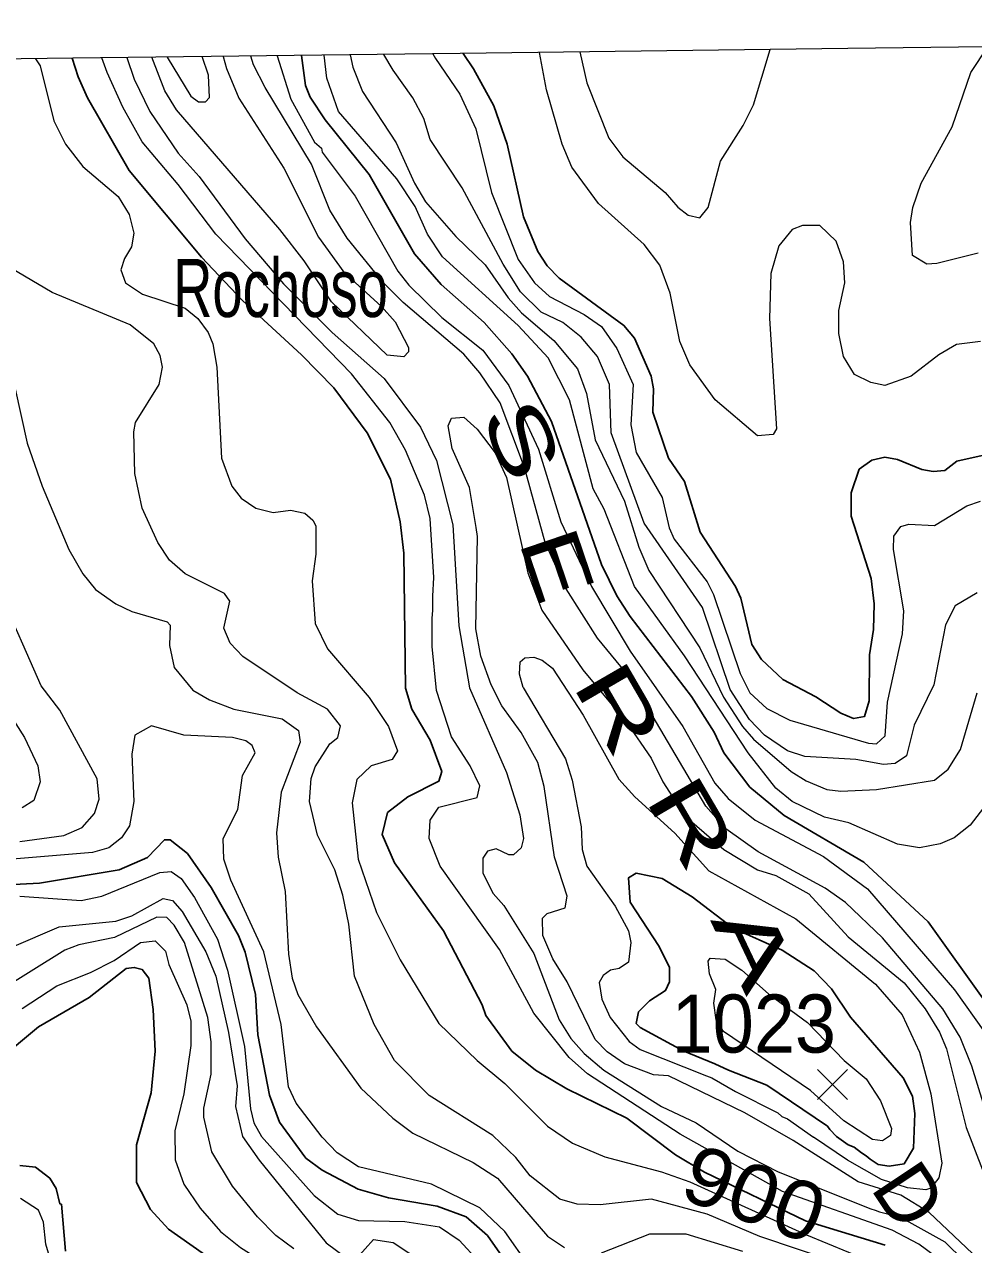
# Model space of a CAD drawing. Extents: x 265 to 291.4, y 7731.5 to 7759.6.
# Drawn here: x 281.951 to 283.257, y 7757.817 to 7759.497 of the extents above; entities that cross this region are included whole.
import ezdxf
from ezdxf.enums import TextEntityAlignment as Align

# ---------------------------------------------------------------- set-up
doc = ezdxf.new("R2010")
doc.units = 0
doc.header["$LTSCALE"] = 0.032
for name, color, linetype, lineweight in [('1', 7, 'Continuous', 25), ('2', 7, 'Continuous', 13), ('21', 7, 'Continuous', 25), ('61', 7, 'Continuous', 13), ('63', 7, 'Continuous', 25)]:
    doc.layers.add(name, color=color, linetype=linetype, lineweight=lineweight)

msp = doc.modelspace()

# ---------------------------------------------------------------- linework, layer by layer
at = {"layer": '1'}
for points in [[(283.1354, 7757.8165), (283.0256, 7757.85), (282.8865, 7757.9171), (282.8467, 7757.941), (282.7798, 7757.9915), (282.697, 7758.0321), (282.6541, 7758.0576), (282.6214, 7758.0838), (282.5856, 7758.1331), (282.5809, 7758.1475), (282.5276, 7758.2493), (282.46, 7758.3432), (282.4433, 7758.3821), (282.4504, 7758.4123), (282.4783, 7758.4338), (282.5212, 7758.4553), (282.5252, 7758.4688), (282.5093, 7758.5118), (282.4838, 7758.5548), (282.4751, 7758.5834), (282.4727, 7758.7695), (282.4679, 7758.8125), (282.4544, 7758.8714), (282.4226, 7758.935), (282.3764, 7758.997), (282.3319, 7759.0424), (282.2508, 7759.1171), (282.1943, 7759.1768), (282.0948, 7759.2961), (282.0376, 7759.3964), (282.0248, 7759.425), (282.0167, 7759.4507)], [(282.3319, 7759.4547), (282.3374, 7759.4131), (282.344, 7759.3972), (282.3645, 7759.3661), (282.425, 7759.2906), (282.4878, 7759.1816), (282.5244, 7759.1394), (282.5833, 7759.0869), (282.6214, 7759.044), (282.6429, 7759.0129), (282.6763, 7758.9509), (282.7447, 7758.7536), (282.7662, 7758.7107), (282.7845, 7758.682), (282.8688, 7758.5723), (282.8999, 7758.5229), (282.9134, 7758.4943), (282.9492, 7758.4474), (282.9961, 7758.4083), (283.1059, 7758.3439), (283.1942, 7758.262), (283.2761, 7758.1475)], [(283.281, 7758.9066), (283.234, 7758.896), (283.2173, 7758.8833), (283.2014, 7758.8817), (283.1855, 7758.8848), (283.1521, 7758.8984), (283.1346, 7758.9015), (283.1171, 7758.8976), (283.0995, 7758.8849), (283.0884, 7758.8523), (283.0884, 7758.8204), (283.1162, 7758.7345), (283.1202, 7758.6995), (283.1194, 7758.6645), (283.1138, 7758.6295), (283.1131, 7758.5659), (283.1067, 7758.5444), (283.0916, 7758.542), (283.0741, 7758.5492), (283.0399, 7758.5714), (282.9946, 7758.5953), (282.9651, 7758.6232), (282.9516, 7758.6438), (282.9365, 7758.7075), (282.9293, 7758.7234), (282.8808, 7758.7982), (282.8593, 7758.8682), (282.837, 7758.9), (282.8155, 7758.9636), (282.8163, 7758.9955), (282.8132, 7759.013), (282.7901, 7759.0655), (282.7758, 7759.083), (282.6867, 7759.1482), (282.67, 7759.1649), (282.6572, 7759.1848), (282.6374, 7759.2325), (282.6151, 7759.3327), (282.5968, 7759.3852), (282.5689, 7759.4362), (282.5547, 7759.4575)], [(281.8825, 7758.3105), (281.9716, 7758.3153), (282.0813, 7758.3336), (282.1203, 7758.3503), (282.1434, 7758.3749), (282.1513, 7758.3749), (282.1752, 7758.3559), (282.2078, 7758.3089), (282.2452, 7758.2429), (282.2547, 7758.2199), (282.269, 7758.1618), (282.2722, 7758.1061), (282.2881, 7758.0234), (282.3017, 7757.986), (282.3382, 7757.9367), (282.3605, 7757.9199), (282.4099, 7757.8937), (282.452, 7757.8817), (282.5189, 7757.8706), (282.5586, 7757.8555), (282.5881, 7757.83), (282.6819, 7757.6956)], [(282.2881, 7757.741), (282.1489, 7757.8388), (282.1243, 7757.8658), (282.1052, 7757.9032), (282.1052, 7757.955), (282.1251, 7758.0266), (282.1306, 7758.0838), (282.1282, 7758.1411), (282.1219, 7758.1841), (282.1131, 7758.196), (282.102, 7758.1991), (282.0909, 7758.1976), (282.04, 7758.1578), (281.97, 7758.1172), (281.9143, 7758.0711)], [(281.9445, 7757.9263), (281.966, 7757.9239), (281.9859, 7757.9088), (281.9946, 7757.8945), (281.9994, 7757.8738), (282.0018, 7757.873), (282.0073, 7757.8086)]]:
    msp.add_lwpolyline(points, dxfattribs=at)
msp.add_lwpolyline([(283.0876, 7758.1307), (283.0613, 7758.1697), (283.0375, 7758.1944), (282.9937, 7758.223), (282.9261, 7758.2532), (282.8696, 7758.2962), (282.8283, 7758.3216), (282.7925, 7758.3288), (282.7821, 7758.3225), (282.7845, 7758.2891), (282.8243, 7758.2278), (282.8386, 7758.1992), (282.8386, 7758.1793), (282.833, 7758.1673), (282.8108, 7758.153), (282.7957, 7758.1379), (282.7925, 7758.122), (282.798, 7758.1164), (282.8571, 7758.0841), (282.9009, 7758.0662), (282.9198, 7758.0575), (282.9723, 7758.0368), (283.0558, 7757.9804), (283.0593, 7757.9761), (283.0685, 7757.9661), (283.0844, 7757.955), (283.0925, 7757.9518), (283.1027, 7757.9438), (283.1091, 7757.9399), (283.1146, 7757.935), (283.1258, 7757.9279), (283.1409, 7757.9255), (283.1616, 7757.9287), (283.1743, 7757.9502), (283.1759, 7757.9979), (283.1727, 7758.0218), (283.16, 7758.0472)], close=True, dxfattribs=at)
at = {"layer": '2'}
msp.add_line((282.5741, 7758.7923), (282.5726, 7758.8047), dxfattribs=at)
for points in [[(283.2634, 7759.1824), (283.2062, 7759.1681), (283.1926, 7759.1673), (283.1727, 7759.1792), (283.1703, 7759.2246), (283.1735, 7759.2452), (283.1847, 7759.2786), (283.2276, 7759.3566), (283.2531, 7759.4314), (283.2765, 7759.4665)], [(281.9662, 7759.4501), (281.9726, 7759.4404), (281.9914, 7759.3646), (282.0073, 7759.3327), (282.0312, 7759.3017), (282.0797, 7759.2603), (282.0948, 7759.2357), (282.1012, 7759.2102), (282.098, 7759.1911), (282.0885, 7759.1752), (282.0837, 7759.1593), (282.0901, 7759.1418), (282.1132, 7759.1259), (282.172, 7759.1068), (282.1895, 7759.0925), (282.2038, 7759.0734), (282.2102, 7759.0575), (282.2158, 7759.0257), (282.2221, 7758.9), (282.2364, 7758.8618), (282.2492, 7758.8451), (282.2691, 7758.8316), (282.2929, 7758.8252), (282.3168, 7758.8284), (282.3367, 7758.8244), (282.3478, 7758.8149), (282.3518, 7758.8069), (282.3518, 7758.7679), (282.347, 7758.7314), (282.351, 7758.6725), (282.3677, 7758.6375), (282.425, 7758.5707), (282.452, 7758.5309), (282.464, 7758.4975), (282.4568, 7758.4855), (282.4282, 7758.4768), (282.4083, 7758.4577), (282.4019, 7758.4259), (282.4099, 7758.3479), (282.4353, 7758.2747), (282.4679, 7758.2095), (282.5212, 7758.122), (282.5737, 7758.0711), (282.6119, 7758.0393), (282.6708, 7757.9804), (282.705, 7757.9573), (282.7495, 7757.9382), (282.8275, 7757.9176), (282.8665, 7757.904), (283.0269, 7757.8309), (283.1139, 7757.7951)], [(283.2149, 7757.7935), (283.1815, 7757.8181), (283.1449, 7757.8372), (282.9941, 7757.8907), (282.853, 7757.9693), (282.7257, 7758.0528), (282.7002, 7758.0751), (282.6517, 7758.1363), (282.6047, 7758.2238), (282.5228, 7758.3384), (282.5077, 7758.3766), (282.5093, 7758.402), (282.5212, 7758.4195), (282.5737, 7758.433), (282.5777, 7758.4489), (282.5642, 7758.4768), (282.5387, 7758.5166), (282.518, 7758.5802), (282.5117, 7758.6407), (282.512, 7758.6796), (282.5127, 7758.6909), (282.5127, 7758.7102), (282.5141, 7758.7361), (282.5093, 7758.8173), (282.5013, 7758.8491), (282.4751, 7758.9111), (282.4536, 7758.9493), (282.4011, 7759.0161), (282.2142, 7759.2086), (282.1625, 7759.2771), (282.1131, 7759.3359), (282.0861, 7759.3836), (282.0646, 7759.4314), (282.0574, 7759.4512)], [(282.0919, 7759.4517), (282.102, 7759.4218), (282.1235, 7759.3773), (282.1625, 7759.32), (282.1911, 7759.2882), (282.2547, 7759.2023), (282.3072, 7759.1402), (282.3741, 7759.0734), (282.4457, 7759.0098), (282.4958, 7758.9427), (282.5177, 7758.8969), (282.5402, 7758.8085), (282.5486, 7758.6696)], [(282.2243, 7759.4533), (282.2288, 7759.4365), (282.2461, 7759.396), (282.3078, 7759.2996), (282.3556, 7759.2046), (282.3902, 7759.1562), (282.4423, 7759.109), (282.4609, 7759.0877), (282.4795, 7759.0525), (282.4795, 7759.0465), (282.4728, 7759.0399), (282.4502, 7759.0419), (282.3733, 7759.1156), (282.3359, 7759.172), (282.3025, 7759.215), (282.1601, 7759.3797), (282.1442, 7759.4059), (282.126, 7759.4521)], [(282.1471, 7759.4524), (282.1799, 7759.3987), (282.1905, 7759.3908), (282.1998, 7759.3908), (282.2055, 7759.3968), (282.2042, 7759.4273), (282.1954, 7759.453)], [(283.3031, 7757.9055), (283.2543, 7758.063), (283.2384, 7758.1029), (283.2145, 7758.1421), (283.1314, 7758.2397), (283.0805, 7758.2883), (283.0526, 7758.3081), (282.9603, 7758.3583), (282.9158, 7758.3901), (282.8887, 7758.4211), (282.7845, 7758.5977), (282.7392, 7758.6526), (282.6962, 7758.7202), (282.6676, 7758.7839), (282.639, 7758.8873), (282.6055, 7758.9764), (282.5777, 7759.0177), (282.5554, 7759.0432), (282.4718, 7759.1143), (282.4449, 7759.1415), (282.3951, 7759.2033), (282.3712, 7759.2418), (282.346, 7759.305), (282.2819, 7759.4106), (282.266, 7759.4418), (282.2624, 7759.4538)], [(282.2987, 7759.4543), (282.3173, 7759.3945), (282.3502, 7759.3351), (282.3597, 7759.3272), (282.3605, 7759.3216), (282.4059, 7759.2611), (282.4647, 7759.1577), (282.4799, 7759.1386), (282.5252, 7759.0941), (282.5817, 7759.0487), (282.6175, 7759.0002), (282.6581, 7758.9127), (282.6891, 7758.8125), (282.7312, 7758.7234), (282.7845, 7758.6343), (282.8569, 7758.5309), (282.9007, 7758.4529), (282.919, 7758.4315), (282.9564, 7758.402), (283.0502, 7758.3519), (283.1107, 7758.3073), (283.2308, 7758.1681), (283.2722, 7758.1093)], [(283.1521, 7758.3686), (283.0852, 7758.398), (283.0518, 7758.406), (283.0073, 7758.4275), (282.985, 7758.4458), (282.9468, 7758.4943), (282.8593, 7758.6279), (282.7901, 7758.7234), (282.7487, 7758.83), (282.7336, 7758.8578), (282.701, 7758.9803), (282.6716, 7759.0384), (282.6302, 7759.083), (282.526, 7759.1776), (282.5053, 7759.2086), (282.4886, 7759.2468), (282.4632, 7759.285), (282.3828, 7759.3773), (282.3669, 7759.4234), (282.3633, 7759.4551)], [(282.3992, 7759.4555), (282.4027, 7759.4385), (282.4162, 7759.4051), (282.4624, 7759.3343), (282.4878, 7759.2786), (282.5029, 7759.2532), (282.5443, 7759.2055), (282.5849, 7759.1665), (282.6167, 7759.1211), (282.635, 7759.1004), (282.6795, 7759.0623), (282.7121, 7759.0233), (282.7241, 7758.9891), (282.736, 7758.9255), (282.7766, 7758.8411), (282.7965, 7758.7775), (282.81, 7758.7457), (282.88, 7758.6391), (282.913, 7758.5712), (282.9389, 7758.5307), (282.9542, 7758.5134), (283.0057, 7758.4688), (283.0264, 7758.4561), (283.055, 7758.4442), (283.0741, 7758.4418), (283.1234, 7758.4442), (283.203, 7758.4569), (283.2221, 7758.472), (283.2388, 7758.4991), (283.2618, 7758.577)], [(283.2618, 7758.7146), (283.2316, 7758.6971), (283.2181, 7758.6709), (283.2022, 7758.5882), (283.1751, 7758.5325), (283.1648, 7758.4903), (283.1489, 7758.48), (283.133, 7758.4784), (283.0948, 7758.4855), (283.0248, 7758.4895), (283.0009, 7758.4975), (282.9691, 7758.5189), (282.9484, 7758.5404), (282.9221, 7758.5818), (282.884, 7758.6948), (282.8036, 7758.8109), (282.7583, 7758.935), (282.7559, 7759.0018), (282.7392, 7759.04), (282.7169, 7759.067), (282.6915, 7759.0869), (282.662, 7759.1012), (282.6334, 7759.1291), (282.6095, 7759.1673), (282.553, 7759.2723), (282.5093, 7759.3391), (282.5005, 7759.3677), (282.4854, 7759.3964), (282.4584, 7759.4346), (282.4454, 7759.4561)], [(282.5129, 7759.457), (282.5165, 7759.4504), (282.5499, 7759.4012), (282.5721, 7759.3534), (282.5936, 7759.2659), (282.6302, 7759.1736), (282.6525, 7759.1418), (282.6732, 7759.1227), (282.7209, 7759.098), (282.7448, 7759.0813), (282.7662, 7759.0511), (282.7885, 7759.0018), (282.7853, 7758.9461), (282.7925, 7758.9079), (282.8283, 7758.8459), (282.8378, 7758.8045), (282.845, 7758.7886), (282.8903, 7758.7298), (282.8991, 7758.7123), (282.9359, 7758.6038), (282.9491, 7758.5772), (282.9723, 7758.5555), (283.0041, 7758.5396), (283.1123, 7758.5078), (283.1234, 7758.507), (283.1354, 7758.5181), (283.1385, 7758.5643), (283.1592, 7758.6582), (283.1608, 7758.69), (283.1465, 7758.7743), (283.1473, 7758.7926), (283.1568, 7758.8061), (283.168, 7758.8093), (283.203, 7758.8077), (283.2475, 7758.8347), (283.2666, 7758.8411)], [(283.2666, 7759.0607), (283.2332, 7759.0567), (283.2093, 7759.0424), (283.1712, 7759.0129), (283.1346, 7759.0002), (283.1155, 7759.0042), (283.0932, 7759.0153), (283.0781, 7759.04), (283.0717, 7759.0718), (283.0717, 7759.1036), (283.0797, 7759.1418), (283.0781, 7759.1705), (283.0677, 7759.1991), (283.0455, 7759.2206), (283.0216, 7759.2206), (283.0073, 7759.215), (282.989, 7759.1927), (282.9778, 7759.1545), (282.9762, 7759.0925), (282.9858, 7758.9406), (282.981, 7758.9326), (282.9596, 7758.931), (282.9015, 7758.9803), (282.8665, 7759.0289), (282.8529, 7759.0607), (282.8394, 7759.1275), (282.8251, 7759.1657), (282.8036, 7759.1943), (282.7408, 7759.2508), (282.7042, 7759.3009), (282.6907, 7759.3327), (282.6692, 7759.4075), (282.6595, 7759.4588)], [(282.7151, 7759.4595), (282.7249, 7759.4171), (282.7551, 7759.3407), (282.7742, 7759.3152), (282.8323, 7759.2659), (282.8498, 7759.246), (282.8641, 7759.2349), (282.88, 7759.2309), (282.8919, 7759.2452), (282.9086, 7759.3089), (282.9397, 7759.3582), (282.954, 7759.3868), (282.9772, 7759.4628)], [(283.0677, 7757.7935), (282.9627, 7757.8285), (282.8901, 7757.8596), (282.8137, 7757.8802), (282.7432, 7757.8722), (282.7114, 7757.873), (282.6875, 7757.8802), (282.6469, 7757.912), (282.627, 7757.9375), (282.5952, 7757.9677), (282.5077, 7758.0226), (282.46, 7758.0711), (282.4321, 7758.1204), (282.4051, 7758.1872), (282.3971, 7758.2588), (282.3892, 7758.2986), (282.378, 7758.3336), (282.3542, 7758.3813), (282.343, 7758.4275), (282.3454, 7758.4593), (282.351, 7758.4752), (282.3709, 7758.507), (282.382, 7758.5158), (282.386, 7758.5317), (282.3677, 7758.5547), (282.3263, 7758.577), (282.2516, 7758.6271), (282.2341, 7758.6454), (282.2253, 7758.6661), (282.2333, 7758.7035), (282.2261, 7758.7139), (282.172, 7758.7409), (282.1505, 7758.76), (282.1346, 7758.7839), (282.1131, 7758.8316), (282.1028, 7758.8793), (282.1012, 7758.9366), (282.1036, 7758.9493), (282.1362, 7759.0018), (282.141, 7759.0257), (282.1378, 7759.0416), (282.129, 7759.0575), (282.0964, 7759.0837), (281.9891, 7759.1283), (281.923, 7759.1673)], [(281.9294, 7759.0352), (281.9548, 7758.9207), (281.9755, 7758.8618), (282.0121, 7758.7743), (282.0312, 7758.7409), (282.0487, 7758.7194), (282.0766, 7758.6995), (282.0988, 7758.6892), (282.1473, 7758.6749), (282.1513, 7758.6701), (282.1505, 7758.6423), (282.1569, 7758.612), (282.1824, 7758.581), (282.2054, 7758.5675), (282.2388, 7758.5547), (282.3057, 7758.5412), (282.3279, 7758.5253), (282.3303, 7758.5094), (282.3041, 7758.4402), (282.2977, 7758.3845), (282.3001, 7758.3511), (282.3096, 7758.3034), (282.3144, 7758.2175), (282.3192, 7758.1841), (282.3271, 7758.1618), (282.3526, 7758.1172), (282.4138, 7758.0329), (282.4576, 7757.9915), (282.4854, 7757.9709), (282.5682, 7757.9303), (282.6016, 7757.9088), (282.6708, 7757.8293), (282.6939, 7757.8133)], [(282.5726, 7758.8047), (282.5633, 7758.8598), (282.5393, 7758.9136), (282.534, 7758.9448), (282.5387, 7758.9555), (282.5553, 7758.9568), (282.5739, 7758.9402), (282.5985, 7758.9076), (282.6144, 7758.8738), (282.6437, 7758.7425), (282.6628, 7758.6908), (282.7193, 7758.6088), (282.7798, 7758.5357), (282.8132, 7758.4871), (282.8291, 7758.4545), (282.8593, 7758.4084), (282.9134, 7758.3614), (282.9596, 7758.3336), (282.985, 7758.3256), (283.0303, 7758.3002), (283.0844, 7758.2413), (283.1616, 7758.1777), (283.1902, 7758.1419), (283.2101, 7758.1101), (283.2197, 7758.087), (283.2467, 7757.9788), (283.2817, 7757.8881)], [(283.2556, 7757.8052), (283.1958, 7757.8616), (283.1566, 7757.8856), (283.098, 7757.904), (283.0085, 7757.961), (282.942, 7757.9988), (282.8371, 7758.05), (282.8165, 7758.0511), (282.7766, 7758.0663), (282.7527, 7758.083), (282.736, 7758.0997), (282.6978, 7758.1793), (282.6779, 7758.2111), (282.6644, 7758.2429), (282.6636, 7758.2668), (282.67, 7758.2731), (282.6947, 7758.2811), (282.6978, 7758.297), (282.6803, 7758.3511), (282.666, 7758.4482), (282.6575, 7758.4813), (282.6342, 7758.5225), (282.6077, 7758.5591), (282.593, 7758.5883), (282.5791, 7758.6275), (282.5718, 7758.6654), (282.5741, 7758.7923)], [(281.9445, 7758.3726), (282.005, 7758.3805), (282.0304, 7758.3917), (282.0471, 7758.4108), (282.0535, 7758.4307), (282.0511, 7758.4585), (281.9994, 7758.5532), (281.9739, 7758.5866), (281.9159, 7758.717)], [(282.5486, 7758.6696), (282.5632, 7758.5839), (282.614, 7758.4676), (282.6326, 7758.4092), (282.6374, 7758.3766), (282.6342, 7758.3638), (282.6239, 7758.3543), (282.6175, 7758.3543), (282.6, 7758.3622), (282.5881, 7758.359), (282.5817, 7758.3495), (282.5817, 7758.3288), (282.596, 7758.301), (282.6103, 7758.2843), (282.6517, 7758.2183), (282.6867, 7758.1268), (282.7026, 7758.1013), (282.7209, 7758.0806), (282.7479, 7758.0576), (282.8275, 7758.0074), (282.8752, 7757.9852), (282.9325, 7757.9462), (282.9882, 7757.9176), (283.1155, 7757.8666), (283.1214, 7757.8651), (283.1274, 7757.8627), (283.1552, 7757.8555), (283.2173, 7757.8213), (283.2706, 7757.7688)], [(282.6372, 7758.5844), (282.6319, 7758.603), (282.6332, 7758.6196), (282.6392, 7758.6255), (282.6518, 7758.6262), (282.6631, 7758.6222), (282.6777, 7758.6109), (282.7196, 7758.5465), (282.7687, 7758.4581), (282.7909, 7758.4338), (282.8458, 7758.3837), (282.8927, 7758.332), (283.0121, 7758.266), (283.1218, 7758.1761), (283.1584, 7758.1339), (283.1823, 7758.0822), (283.1982, 7758.025), (283.2133, 7757.9295), (283.2093, 7757.9096), (283.1982, 7757.8953), (283.191, 7757.8929), (283.1659, 7757.8957), (283.1301, 7757.907), (283.0836, 7757.9336), (283.0364, 7757.9654)], [(282.6372, 7758.5844), (282.6954, 7758.4861), (282.7047, 7758.4569), (282.7169, 7758.3925), (282.7185, 7758.3614), (282.7249, 7758.3384), (282.7638, 7758.2835), (282.7821, 7758.2493), (282.7853, 7758.2334), (282.7821, 7758.2063), (282.7694, 7758.1976), (282.7575, 7758.1952), (282.7472, 7758.188), (282.7416, 7758.1785), (282.7455, 7758.1554), (282.7567, 7758.13), (282.7829, 7758.0973), (282.798, 7758.0862), (282.8895, 7758.0496), (282.8969, 7758.0471), (282.9293, 7758.0281), (282.9874, 7757.9987), (282.9932, 7757.994), (283.0009, 7757.9907), (283.0364, 7757.9654)], [(281.9302, 7758.5484), (281.9509, 7758.5158), (281.9692, 7758.4768), (281.9723, 7758.4545), (281.9636, 7758.4291), (281.9477, 7758.4187)], [(282.5109, 7757.9008), (282.4107, 7757.9247), (282.3812, 7757.9438), (282.3605, 7757.9653), (282.3247, 7758.0122), (282.3144, 7758.0345), (282.3041, 7758.1204), (282.2802, 7758.2207), (282.2349, 7758.3193), (282.2253, 7758.3479), (282.2245, 7758.3766), (282.2444, 7758.4163), (282.2508, 7758.4633), (282.2683, 7758.4943), (282.2643, 7758.5046), (282.2555, 7758.511), (282.2373, 7758.5158), (282.1704, 7758.5189), (282.1259, 7758.5317), (282.1028, 7758.5189), (282.0988, 7758.4927), (282.1012, 7758.4275), (282.0956, 7758.3941), (282.0845, 7758.3774), (282.067, 7758.3638), (282.0447, 7758.3575), (281.857, 7758.3415)], [(283.3127, 7758.4863), (283.2857, 7758.4386), (283.2523, 7758.3949), (283.23, 7758.3773), (283.2109, 7758.3694), (283.1823, 7758.3638), (283.1521, 7758.3686)], [(281.9445, 7758.297), (282.0288, 7758.2914), (282.0575, 7758.297), (282.137, 7758.3296), (282.1529, 7758.3312), (282.1665, 7758.3217), (282.1847, 7758.2954), (282.2166, 7758.2382), (282.2301, 7758.1952), (282.2539, 7758.0902), (282.2619, 7758.0043), (282.2667, 7757.9852), (282.277, 7757.9661), (282.3494, 7757.8849), (282.382, 7757.8595), (282.4107, 7757.8507), (282.4743, 7757.8491), (282.522, 7757.842), (282.5491, 7757.8237), (282.5761, 7757.7943)], [(281.9334, 7758.227), (281.9986, 7758.2548), (282.0766, 7758.2628), (282.0988, 7758.27), (282.1418, 7758.2938), (282.1545, 7758.2914), (282.168, 7758.2763), (282.2006, 7758.2207), (282.2142, 7758.1872), (282.2317, 7758.1093), (282.2436, 7758.0361), (282.2412, 7758.0075), (282.2508, 7757.9661), (282.2738, 7757.9335), (282.3661, 7757.8197), (282.3947, 7757.799)], [(282.3216, 7757.8118), (282.2969, 7757.8301), (282.2714, 7757.8555), (282.2372, 7757.8977), (282.2086, 7757.9454), (282.1975, 7757.9931), (282.1975, 7758.0051), (282.2078, 7758.052), (282.2078, 7758.0966), (282.203, 7758.13), (282.1712, 7758.2334), (282.1569, 7758.2572), (282.1466, 7758.2676), (282.133, 7758.2684), (282.075, 7758.2405), (282.0257, 7758.2302), (282.0066, 7758.223), (281.9175, 7758.1673)], [(281.9477, 7758.1427), (281.9954, 7758.1737), (282.0416, 7758.192), (282.0742, 7758.2087), (282.1108, 7758.2334), (282.1307, 7758.2357), (282.145, 7758.2214), (282.1497, 7758.2032), (282.1744, 7758.1475), (282.18, 7758.1252), (282.18, 7758.0918), (282.1704, 7758.025), (282.1577, 7757.9741), (282.1585, 7757.9343), (282.1704, 7757.9009), (282.1927, 7757.8675), (282.2205, 7757.8356), (282.2484, 7757.8133), (282.3041, 7757.7783), (282.3709, 7757.7258)], [(282.7177, 7757.7068), (282.7026, 7757.7147), (282.6827, 7757.7465), (282.6453, 7757.7879), (282.6119, 7757.8356), (282.5777, 7757.8682), (282.5109, 7757.9008)], [(281.9946, 7757.7704), (281.9803, 7757.8181), (281.9771, 7757.8484), (281.97, 7757.8651), (281.9453, 7757.881)], [(282.4083, 7757.799), (282.4313, 7757.8245), (282.4584, 7757.8205), (282.4998, 7757.7927)], [(282.7448, 7757.8062), (282.8116, 7757.8324), (282.8609, 7757.8324), (282.9389, 7757.8086)]]:
    msp.add_lwpolyline(points, dxfattribs=at)
msp.add_lwpolyline([(283.0782, 7757.988), (283.0324, 7758.0298), (282.9128, 7758.1109), (282.9029, 7758.1268), (282.8995, 7758.1501), (282.9023, 7758.1689), (282.8935, 7758.1904), (282.8919, 7758.2079), (282.8943, 7758.2119), (282.915, 7758.2103), (282.9381, 7758.1952), (282.9747, 7758.1626), (283.0282, 7758.1234), (283.0787, 7758.0709), (283.1091, 7758.0456), (283.129, 7758.0154), (283.1441, 7757.9772), (283.1425, 7757.9677), (283.1314, 7757.9605), (283.1178, 7757.9621)], close=True, dxfattribs=at)
at = {"layer": '21'}
for p, q in [((283.0422, 7758.0584), (283.0834, 7758.0172)), ((283.0834, 7758.0584), (283.0422, 7758.0172))]:
    msp.add_line(p, q, dxfattribs=at)
at = {"layer": '63', "lineweight": 13}
msp.add_lwpolyline([(285.7494, 7759.4974), (285.2163, 7759.4908), (284.6831, 7759.4841), (284.15, 7759.4775), (283.6169, 7759.4708), (283.0837, 7759.4641), (282.5506, 7759.4574), (282.0174, 7759.4507), (281.4843, 7759.444), (280.9511, 7759.4372), (280.418, 7759.4305), (279.8848, 7759.4237), (279.3517, 7759.4169), (278.8185, 7759.4101), (278.2854, 7759.4032), (277.7522, 7759.3964), (277.2191, 7759.3895), (276.6859, 7759.3826), (276.1528, 7759.3757), (275.6196, 7759.3688), (275.0864, 7759.3619), (274.5533, 7759.355), (274.0201, 7759.348)], dxfattribs=at)

# ---------------------------------------------------------------- texts
at = {"layer": '61', "width": 0.7}
msp.add_text('Rochoso', height=0.08, dxfattribs=at).set_placement((282.1554, 7759.0946))
at = {"layer": '61'}
for s, rotation, width, p in [('S', 293.476, 1.5, (282.5986, 7758.9101)), ('E', 288.731, 1.35, (282.646, 7758.7401)), ('R', 300.11, 1.6, (282.7343, 7758.5355)), ('R', 300.324, 1.6, (282.8346, 7758.3781)), ('A', 295.319, 1.65, (282.9193, 7758.2112)), ('900', 340.677, 1.1, (282.9419, 7757.8497))]:
    msp.add_text(s, height=0.08, rotation=rotation, dxfattribs=dict(at, width=width)).set_placement(p, align=Align.CENTER)
at = {"layer": '61', "width": 0.95}
msp.add_text('1023', height=0.08, dxfattribs=at).set_placement((282.9545, 7758.0818), align=Align.CENTER)
at = {"layer": '61'}
msp.add_text('D', height=0.08, rotation=303.713, dxfattribs=at).set_placement((283.1353, 7757.863), align=Align.CENTER)

doc.saveas('drawing.dxf')
